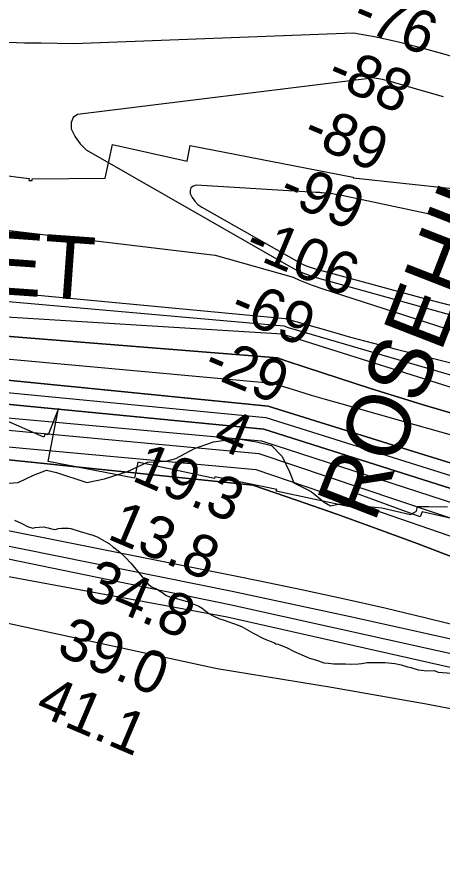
# Model space of a CAD drawing. Extents: x 3279314 to 3317160, y 734079 to 759431.
# Drawn here: x 3288528 to 3289202, y 752535 to 753859 of the extents above; entities that cross this region are included whole.
import ezdxf

# ---------------------------------------------------------------- set-up
doc = ezdxf.new("R2010")
doc.units = 0
for name, color, linetype in [('V-RIVR-EDGE', 7, 'Continuous'), ('V-RIVR-RANG', 7, 'Continuous'), ('V-RRAP-RVMT', 7, 'Continuous'), ('V-RRAP-RVMT-IDEN', 7, 'Continuous'), ('V-SITE-VEGE', 7, 'Continuous'), ('V-TOPO-DPTH', 7, 'Continuous'), ('V-TOPO-GNAM-IDEN', 7, 'Continuous'), ('V-TOPO-MAJR', 7, 'Continuous'), ('V-TOPO-MINR', 7, 'Continuous'), ('V-TOPO-WATR', 7, 'Continuous')]:
    doc.layers.add(name, color=color, linetype=linetype)

msp = doc.modelspace()

# ---------------------------------------------------------------- linework, layer by layer
at = {"layer": 'V-RIVR-EDGE'}
msp.add_lwpolyline([(3288515.4, 753120.8), (3288530.2, 753121.6), (3288554.5, 753133.3), (3288575, 753141.5), (3288591, 753137.6), (3288638.8, 753121.8), (3288666.7, 753127.4), (3288703.6, 753139), (3288735, 753154.2), (3288764.1, 753155.8), (3288779.8, 753159.7), (3288809.4, 753175.7), (3288839.4, 753186.1), (3288875.9, 753191.6), (3288907.6, 753186.4), (3288931.5, 753180.2), (3288948.4, 753162.8), (3288960.1, 753138.8), (3288966.6, 753121), (3288976.1, 753116.6), (3288994.4, 753107.5), (3289014.7, 753090.5), (3289024.7, 753084.8), (3289039.5, 753088.2), (3289106, 753081.5), (3289151.6, 753071), (3289161.2, 753076.6), (3289162.5, 753083.6), (3289180.3, 753084), (3289210.3, 753083)], dxfattribs=at)
at = {"layer": 'V-RRAP-RVMT'}
for p, q in [((3288667.8, 753603.9), (3288679.6, 753656.8)), ((3288679.6, 753656.8), (3288797.7, 753630.7)), ((3288797.7, 753630.7), (3288802.4, 753655.3)), ((3288802.4, 753655.3), (3289061, 753605.2)), ((3288435, 753617.4), (3288547.5, 753603.3)), ((3288547.5, 753603.3), (3288547.1, 753600.1)), ((3288552.4, 753600.2), (3288552.6, 753602.8)), ((3288552.6, 753602.8), (3288667.8, 753603.9)), ((3289061, 753605.2), (3289060.8, 753604.2)), ((3289060.8, 753604.2), (3289217.9, 753587.1)), ((3288547.1, 753600.1), (3288552.4, 753600.2)), ((3288594, 753238.9), (3288577.5, 753197.1)), ((3288577.7, 753155.1), (3288594, 753238.9)), ((3288570.6, 753193.5), (3288493.1, 753227.4)), ((3288573, 753198.9), (3288570.6, 753193.5)), ((3288577.5, 753197.1), (3288573, 753198.9)), ((3288714.7, 753128.4), (3288577.7, 753155.1)), ((3288719.9, 753154.1), (3288714.7, 753128.4)), ((3288841.2, 753128), (3288719.9, 753154.1)), ((3288841.7, 753130.5), (3288841.2, 753128)), ((3288939.7, 753110.6), (3288841.7, 753130.5)), ((3288939.1, 753108), (3288939.7, 753110.6)), ((3289055.2, 753083.4), (3288939.1, 753108)), ((3289060.1, 753106.4), (3289055.2, 753083.4)), ((3289167.1, 753067.5), (3289060.1, 753106.4)), ((3289170.2, 753075.4), (3289167.1, 753067.5)), ((3289271.5, 753052.3), (3289170.2, 753075.4))]:
    msp.add_line(p, q, dxfattribs=at)
at = {"layer": 'V-SITE-VEGE'}
for points in [[(3288524.4, 753062.3), (3288530.2, 753059.6), (3288534.1, 753058.1), (3288537.2, 753056.5), (3288545, 753052.3), (3288553.2, 753049.6), (3288557.1, 753050.4), (3288563.3, 753051.2), (3288571.1, 753051.3), (3288574.6, 753050.5), (3288577.7, 753050.1), (3288582.8, 753048.6), (3288586.3, 753047.8), (3288589.8, 753047.5), (3288593.7, 753048.7), (3288598.7, 753049.5), (3288603.8, 753049.5), (3288610.1, 753049.7), (3288613.4, 753048.7), (3288626.7, 753044.8), (3288648.4, 753038.3), (3288655.1, 753035.6), (3288675.1, 753024.6), (3288680.7, 753019.6), (3288683.5, 753018), (3288694.1, 753009.1), (3288700.2, 753003.1), (3288708.6, 752994.2), (3288714.2, 752987.1), (3288735.9, 752960.6), (3288742.6, 752956.1), (3288748.2, 752954), (3288757.7, 752947.9), (3288764.3, 752943.5), (3288772.1, 752939.7), (3288778.8, 752938.6), (3288797.7, 752933.1), (3288816.6, 752926), (3288821.6, 752922.7), (3288832.2, 752914.5), (3288838.9, 752910.6), (3288848.9, 752905.7), (3288855, 752904.1), (3288878.9, 752895.9), (3288885, 752893.1), (3288903.4, 752882.7), (3288920.1, 752874.4), (3288936.2, 752867.9), (3288938.4, 752866.2), (3288941.8, 752865.7), (3288956.2, 752859.7), (3288966.2, 752854.7)], [(3288966.2, 752854.7), (3288991.8, 752843.8), (3289001.3, 752841), (3289005.7, 752839.4), (3289014.1, 752836.1), (3289021.8, 752835.6), (3289030.2, 752834.6), (3289048.5, 752834.7), (3289058.5, 752834.2), (3289069, 752834.8), (3289074.6, 752835.3), (3289082.9, 752836.5), (3289111.7, 752836.7), (3289126.7, 752835.1), (3289136.7, 752832.9), (3289146.7, 752829.6), (3289152.3, 752828.6), (3289163.9, 752825.3), (3289177.8, 752823.7), (3289188.9, 752823.8), (3289195.6, 752821.6), (3289216.7, 752820)]]:
    msp.add_lwpolyline(points, dxfattribs=at)
at = {"layer": 'V-TOPO-DPTH'}
for p, q in [((3288941, 753319), (3287692.6, 753419.3)), ((3288941, 753319), (3287692.6, 753419.3)), ((3288954.4, 753314.3), (3288941, 753319)), ((3288954.4, 753314.3), (3288941, 753319)), ((3288986.2, 753303.7), (3288954.4, 753314.3)), ((3288986.2, 753303.7), (3288954.4, 753314.3)), ((3289088.3, 753270.8), (3288986.2, 753303.7)), ((3289088.3, 753270.8), (3288986.2, 753303.7)), ((3289171.5, 753244.9), (3289088.3, 753270.8)), ((3289171.5, 753244.9), (3289088.3, 753270.8)), ((3289255, 753220.1), (3289171.5, 753244.9)), ((3289255, 753220.1), (3289171.5, 753244.9))]:
    msp.add_line(p, q, dxfattribs=at)
for points in [[(3287702, 753391.4), (3288933.2, 753278.8)], [(3287702, 753391.4), (3288933.2, 753278.8)], [(3288926.2, 753242.7), (3287671.1, 753367.5)], [(3288926.2, 753242.7), (3287671.1, 753367.5)], [(3287642.3, 753330), (3288919.1, 753206.3)], [(3288919.1, 753206.3), (3287642.3, 753330)], [(3287613, 753288.7), (3288911.6, 753167.8)], [(3287613, 753288.7), (3288911.6, 753167.8)], [(3288933.2, 753278.8), (3288950.3, 753273.6), (3288972.4, 753266.8), (3288994.5, 753260.2), (3289016.7, 753253.7), (3289038.9, 753247.3), (3289158.2, 753213.4), (3289240.1, 753190.3), (3289322.1, 753167.4), (3289404.1, 753144.7), (3289486.2, 753122.2), (3290053.7, 752967.9), (3290075.8, 752962), (3290097.9, 752956.2), (3290120, 752950.6), (3290331.6, 752827.9), (3290344.6, 752819.8), (3290357.6, 752811.6), (3290370.6, 752803.5), (3290383.7, 752795.5), (3290396.9, 752787.9), (3290410.5, 752780.8)], [(3288933.2, 753278.8), (3288950.3, 753273.6), (3288972.4, 753266.8), (3288994.5, 753260.2), (3289016.7, 753253.7), (3289038.9, 753247.3), (3289158.2, 753213.4), (3289240.1, 753190.3), (3289322.1, 753167.4), (3289404.1, 753144.7), (3289486.2, 753122.2), (3290053.7, 752967.9), (3290075.8, 752962), (3290097.9, 752956.2), (3290120, 752950.6), (3290331.6, 752827.9), (3290344.6, 752819.8), (3290357.6, 752811.6), (3290370.6, 752803.5), (3290383.7, 752795.5), (3290396.9, 752787.9), (3290410.5, 752780.8)], [(3288901.9, 753117.5), (3287583.5, 753254.2)], [(3290430.9, 752719), (3290392, 752736.4), (3290353.5, 752754.8), (3290263.7, 752799.8), (3290256.1, 752803.7), (3290248.6, 752807.8), (3290241.2, 752812.1), (3290233.9, 752816.4), (3290226.5, 752820.8), (3290219.1, 752824.9), (3290211.5, 752828.7), (3290203.8, 752832.4), (3290134.3, 752863.5), (3290108.6, 752874.4), (3290082.7, 752884.7), (3290056.4, 752894), (3290029.8, 752902.6), (3289712.1, 752999.7), (3289575.3, 753041.6), (3289438.5, 753083.6), (3289301.7, 753125.9), (3289165, 753168.3), (3288926.2, 753242.7)], [(3290430.9, 752719), (3290392, 752736.4), (3290353.5, 752754.8), (3290263.7, 752799.8), (3290256.1, 752803.7), (3290248.6, 752807.8), (3290241.2, 752812.1), (3290233.9, 752816.4), (3290226.5, 752820.8), (3290219.1, 752824.9), (3290211.5, 752828.7), (3290203.8, 752832.4), (3290134.3, 752863.5), (3290108.6, 752874.4), (3290082.7, 752884.7), (3290056.4, 752894), (3290029.8, 752902.6), (3289712.1, 752999.7), (3289575.3, 753041.6), (3289438.5, 753083.6), (3289301.7, 753125.9), (3289165, 753168.3), (3288926.2, 753242.7)], [(3288919.1, 753206.3), (3289896.3, 752896.3)], [(3289896.3, 752896.3), (3288919.1, 753206.3)], [(3288911.6, 753167.8), (3289352, 753019.6), (3289470.5, 752979.4), (3289588.8, 752938.7), (3289706.9, 752897.2), (3289824.8, 752855.3), (3290024.6, 752783.7), (3290042.5, 752777.1), (3290060.2, 752770.2), (3290077.8, 752762.9), (3290095.2, 752755.3), (3290137.3, 752736.5), (3290146.1, 752732.7), (3290154.9, 752728.9), (3290163.8, 752725.3), (3290172.7, 752721.7), (3290181.6, 752718.2), (3290190.5, 752714.8), (3290199.5, 752711.4), (3290208.4, 752708), (3290373.4, 752645.8), (3290413, 752631.1)], [(3288911.6, 753167.8), (3289352, 753019.6), (3289470.5, 752979.4), (3289588.8, 752938.7), (3289706.9, 752897.2), (3289824.8, 752855.3), (3290024.6, 752783.7), (3290042.5, 752777.1), (3290060.2, 752770.2), (3290077.8, 752762.9), (3290095.2, 752755.3), (3290137.3, 752736.5), (3290146.1, 752732.7), (3290154.9, 752728.9), (3290163.8, 752725.3), (3290172.7, 752721.7), (3290181.6, 752718.2), (3290190.5, 752714.8), (3290199.5, 752711.4), (3290208.4, 752708), (3290373.4, 752645.8), (3290413, 752631.1)], [(3290439.6, 752571.9), (3290399.1, 752586.8), (3290392.6, 752589.2), (3290348.9, 752605.7), (3290305.1, 752621.9), (3290261.2, 752637.6), (3290217.1, 752653.1), (3290123.8, 752685.3), (3290087.3, 752697.5), (3290050.6, 752709.2), (3290013.8, 752720.1), (3289976.7, 752730.6), (3289351.3, 752951.4), (3289314.3, 752966.9), (3289225.7, 753001), (3289162.3, 753025), (3289098.7, 753048.6), (3289034.8, 753071.4), (3288970.8, 753093.8), (3288901.9, 753117.5)]]:
    msp.add_lwpolyline(points, dxfattribs=at)
at = {"layer": 'V-TOPO-MAJR'}
for points in [[(3289918.8, 753390), (3289042.9, 753576.1), (3289037.9, 753577.1), (3289033, 753577.9), (3289028, 753578.7), (3289022.9, 753579.3), (3289011.9, 753580.5), (3289010.6, 753580.6), (3289009.4, 753580.7), (3289008.1, 753580.8), (3289006.8, 753580.8), (3289005.5, 753580.9), (3289004.2, 753580.9), (3289002.9, 753581), (3289001.6, 753581.1), (3288812.1, 753592.5), (3288807.2, 753591), (3288803.8, 753588.5), (3288802.4, 753584.4), (3288802.5, 753579.3), (3288805.8, 753572.9), (3288809.9, 753567), (3288815, 753562.2), (3288821, 753557.9), (3288974.7, 753470.7), (3288980.5, 753467.7), (3288986.5, 753465), (3288992.6, 753462.7), (3288998.9, 753460.8), (3289173.7, 753413.2), (3289267.8, 753388.8)], [(3287687.9, 753434.7), (3288948.4, 753357.4)], [(3288948.4, 753357.4), (3288951.6, 753356.2), (3288964.7, 753351.9), (3289520.1, 753176.8), (3289617, 753147.1), (3289714.2, 753118.6), (3289811.8, 753091.8), (3289909.8, 753066.1), (3290094.5, 753019.4), (3290100.4, 753018), (3290106.3, 753016.8), (3290112.3, 753015.7), (3290118.2, 753014.8), (3290667.7, 752762.8)], [(3287547.5, 753199.7), (3288865.2, 752928.8)], [(3288865.2, 752928.8), (3289444.6, 752800.1)]]:
    msp.add_lwpolyline(points, dxfattribs=at)
at = {"layer": 'V-TOPO-MINR'}
for p, q in [((3287692.6, 753419.3), (3288941, 753319)), ((3288941, 753319), (3288954.4, 753314.3)), ((3288954.4, 753314.3), (3288986.2, 753303.7)), ((3288986.2, 753303.7), (3289088.3, 753270.8)), ((3289088.3, 753270.8), (3289171.5, 753244.9)), ((3289171.5, 753244.9), (3289255, 753220.1))]:
    msp.add_line(p, q, dxfattribs=at)
for points in [[(3291155.4, 752839), (3291098.9, 752862.9), (3291008.7, 752942.3), (3290845.1, 753101), (3290636.4, 753259.8), (3290266.7, 753469.8), (3290044.4, 753552.8), (3290008.7, 753563.3), (3289972.9, 753573.8), (3289203, 753800.6), (3289167.9, 753810.2), (3289132.6, 753819.1), (3289097.1, 753826.7), (3289061.3, 753833.4), (3288618.3, 753816.6), (3288592.5, 753817), (3288566.7, 753817.3), (3288565.5, 753817.3), (3288540.3, 753817.7), (3288515, 753818.3), (3288489.9, 753819.4), (3288474.9, 753820.2)], [(3289203.9, 753732.7), (3289179.8, 753739.6), (3289155.7, 753746.4), (3289113.9, 753758.3), (3289110.7, 753759.1), (3289107.5, 753759.9), (3289104.2, 753760.6), (3289101, 753761.2), (3289091.4, 753762.8), (3289090.6, 753762.9), (3289089.9, 753762.9), (3289089.2, 753762.9), (3289088.5, 753762.8), (3289087.8, 753762.7), (3289087.1, 753762.4), (3289086.5, 753762.1), (3289085.9, 753761.7), (3288624.1, 753704.7), (3288617.2, 753699.9), (3288614.4, 753691.9), (3288614.4, 753681.9), (3288620.5, 753669.2), (3288628.2, 753657.9), (3288638, 753648.4), (3288957.7, 753465.3), (3288969.3, 753459.2), (3288981.2, 753453.8), (3288993.5, 753449.2), (3289006, 753445.2), (3289715.4, 753248.6)], [(3287736.7, 753526.1), (3287807.9, 753515.5), (3288149.8, 753509), (3288503.2, 753522.2), (3288842.2, 753481.8), (3288965.8, 753447)], [(3287736.7, 753500.4), (3287749.3, 753494.8), (3288953.2, 753381.7)], [(3287755.9, 753475.3), (3288950.8, 753369.7)], [(3288965.8, 753447), (3288975.9, 753442.2), (3288994.1, 753434.8), (3289012.7, 753428.2), (3289305.7, 753334.1), (3289439.9, 753292.6), (3290099, 753114.1), (3290282.6, 753045.8), (3290819, 752815.6), (3291131.4, 752684.8)], [(3287702, 753391.4), (3288933.2, 753278.8)], [(3288953.2, 753381.7), (3289020.6, 753362.2), (3289056.7, 753352), (3289092.8, 753342.2), (3289129.1, 753333), (3289165.5, 753324.1), (3290115.9, 753083), (3290477.3, 752926.7), (3290793.5, 752778.9), (3291129.6, 752671.2)], [(3287671.1, 753367.5), (3288926.2, 753242.7)], [(3288950.8, 753369.7), (3288957.9, 753367.4), (3289817.4, 753116.4), (3289865.7, 753103.4), (3289914.3, 753091.6), (3289963.4, 753081.8), (3290141.2, 753034.9), (3290463.1, 752895.6), (3290810.3, 752736.5), (3291125.3, 752656.2)], [(3287665.3, 753346.3), (3288922.6, 753224.5)], [(3287642.3, 753330), (3288919.1, 753206.3)], [(3287652.2, 753302.2), (3288915.5, 753187.9)], [(3288933.2, 753278.8), (3288950.3, 753273.6), (3288972.4, 753266.8), (3288994.5, 753260.2), (3289016.7, 753253.7), (3289038.9, 753247.3), (3289158.2, 753213.4), (3289240.1, 753190.3), (3289322.1, 753167.4), (3289404.1, 753144.7), (3289486.2, 753122.2), (3290053.7, 752967.9), (3290075.8, 752962), (3290097.9, 752956.2), (3290120, 752950.6), (3290331.6, 752827.9), (3290344.6, 752819.8), (3290357.6, 752811.6), (3290370.6, 752803.5), (3290383.7, 752795.5), (3290396.9, 752787.9), (3290410.5, 752780.8)], [(3287621, 753259.9), (3288906.7, 753142.6)], [(3287583.5, 753254.2), (3288901.9, 753117.5)], [(3288926.2, 753242.7), (3289165, 753168.3), (3289301.7, 753125.9), (3289438.5, 753083.6), (3289575.3, 753041.6), (3289712.1, 752999.7), (3290029.8, 752902.6), (3290056.4, 752894), (3290082.7, 752884.7), (3290108.6, 752874.4), (3290134.3, 752863.5), (3290203.8, 752832.4), (3290211.5, 752828.7), (3290219.1, 752824.9), (3290226.5, 752820.8), (3290233.9, 752816.4), (3290241.2, 752812.1), (3290248.6, 752807.8), (3290256.1, 752803.7), (3290263.7, 752799.8), (3290353.5, 752754.8), (3290392, 752736.4), (3290430.9, 752719)], [(3287592, 753229.8), (3288874, 752973.9)], [(3288922.6, 753224.5), (3289490.3, 753046.2)], [(3287590.1, 753207.9), (3288869.3, 752949.7)], [(3288919.1, 753206.3), (3289896.3, 752896.3)], [(3288915.5, 753187.9), (3289782, 752906.2), (3289829.7, 752890.3), (3289877.2, 752873.9), (3289924.4, 752856.8), (3289971.5, 752839.2), (3289999.2, 752828.6), (3290032.1, 752815.5), (3290064.7, 752801.9), (3290097, 752787.4), (3290129.1, 752772.4), (3290196.1, 752740.1), (3290211.2, 752733), (3290226.5, 752726.2), (3290242, 752719.7), (3290257.5, 752713.5), (3290273.2, 752707.4), (3290288.8, 752701.5), (3290304.5, 752695.6), (3290320.2, 752689.7), (3290454.6, 752639.8)], [(3287568.6, 753147.8), (3288861.4, 752909.2)], [(3288906.7, 753142.6), (3289091.4, 753079.5), (3289210.9, 753038.5), (3289330.3, 752997.4), (3289449.6, 752956), (3289568.9, 752914.3), (3290046.5, 752747), (3290051.4, 752745.2), (3290056.3, 752743.4), (3290061.2, 752741.4), (3290066, 752739.4), (3290078.5, 752734), (3290080.9, 752733), (3290083.4, 752731.9), (3290085.9, 752730.9), (3290088.4, 752729.9), (3290090.9, 752728.9), (3290093.4, 752727.9), (3290095.9, 752727), (3290098.4, 752726), (3290292.9, 752651.6), (3290335.1, 752635.6), (3290377.4, 752619.9), (3290419.8, 752604.4)], [(3287495.5, 753119.9), (3288845.5, 752827.1)], [(3288901.9, 753117.5), (3288970.8, 753093.8), (3289034.8, 753071.4), (3289098.7, 753048.6), (3289162.3, 753025), (3289225.7, 753001), (3289314.3, 752966.9), (3289351.3, 752951.4), (3289976.7, 752730.6), (3290013.8, 752720.1), (3290050.6, 752709.2), (3290087.3, 752697.5), (3290123.8, 752685.3), (3290217.1, 752653.1), (3290261.2, 752637.6), (3290305.1, 752621.9), (3290348.9, 752605.7), (3290392.6, 752589.2), (3290399.1, 752586.8), (3290439.6, 752571.9)], [(3288874, 752973.9), (3288913.2, 752966.1), (3288979.2, 752952.5), (3289045.2, 752938.3), (3289110.9, 752923.2), (3289176.5, 752907.5), (3289990.9, 752706.7), (3290019.4, 752699.2), (3290047.7, 752691.2), (3290075.7, 752682.4), (3290103.6, 752673), (3290149.4, 752656.8), (3290193.4, 752640.8), (3290237.2, 752624.3), (3290280.7, 752607), (3290324, 752589.2), (3290346.9, 752579.6), (3290378.7, 752566.7), (3290410.9, 752554.5)], [(3288869.3, 752949.7), (3289061.3, 752908.3), (3289205.9, 752876.5), (3289350.4, 752843.9), (3289494.6, 752810), (3289638.6, 752775.3), (3290004.9, 752685.4), (3290024.9, 752680.1), (3290044.9, 752674.4), (3290064.6, 752668), (3290084.2, 752661.2), (3290109.1, 752652), (3290140.9, 752639.8), (3290172.4, 752627.1), (3290203.6, 752613.4), (3290234.5, 752599.2), (3290291.1, 752572.3), (3290314.9, 752561.5), (3290339, 752551.3), (3290363.5, 752542.1), (3290388.2, 752533.6), (3290413, 752525.3)], [(3288861.4, 752909.2), (3289871.7, 752681.2)], [(3288845.5, 752827.1), (3289026.7, 752797.5), (3289179.8, 752770.6), (3289332.4, 752741.3), (3289484.3, 752708.5), (3289635.7, 752673.2), (3289988.5, 752586.7), (3290008.4, 752581.1), (3290028, 752574.7), (3290047.2, 752567.1), (3290066.1, 752558.6), (3290094.8, 752544.5), (3290099.9, 752542.1), (3290105, 752539.7), (3290110.2, 752537.5), (3290115.5, 752535.4), (3290120.7, 752533.3), (3290125.9, 752531.1), (3290131.1, 752528.8), (3290136.2, 752526.4), (3290139.3, 752524.9), (3290142.2, 752521.6), (3291142.8, 752203.9)]]:
    msp.add_lwpolyline(points, dxfattribs=at)
at = {"layer": 'V-TOPO-WATR'}
for points in [[(3287613, 753288.7), (3288911.6, 753167.8)], [(3288911.6, 753167.8), (3289352, 753019.6), (3289470.5, 752979.4), (3289588.8, 752938.7), (3289706.9, 752897.2), (3289824.8, 752855.3), (3290024.6, 752783.7), (3290042.5, 752777.1), (3290060.2, 752770.2), (3290077.8, 752762.9), (3290095.2, 752755.3), (3290137.3, 752736.5), (3290146.1, 752732.7), (3290154.9, 752728.9), (3290163.8, 752725.3), (3290172.7, 752721.7), (3290181.6, 752718.2), (3290190.5, 752714.8), (3290199.5, 752711.4), (3290208.4, 752708), (3290373.4, 752645.8), (3290413, 752631.1)]]:
    msp.add_lwpolyline(points, dxfattribs=at)

# ---------------------------------------------------------------- texts
at = {"layer": 'V-RIVR-RANG'}
for s, rotation, p in [('-76', 337.241, (3289056, 753846.6)), ('-88', 337.241, (3289016.1, 753754.9)), ('-89', 337.241, (3288977.9, 753662.5)), ('-99', 337.241, (3288940, 753569.9)), ('-106', 337.241, (3288885.8, 753484.2)), ('-69', 337.241, (3288862.2, 753385.7)), ('-29', 337.241, (3288820.4, 753294.8)), ('4', 337.241, (3288835.5, 753180)), ('19.3', 336.9683, (3288708.1, 753125.6)), ('13.8', 336.9683, (3288669.3, 753033.5)), ('34.8', 336.9683, (3288630.4, 752941.4)), ('39.0', 336.9683, (3288588.8, 752850.4)), ('41.1', 336.9683, (3288554.8, 752756.2))]:
    msp.add_text(s, height=67, rotation=rotation, dxfattribs=at).set_placement(p)
at = {"layer": 'V-RRAP-RVMT-IDEN'}
msp.add_text('REVET', height=100, rotation=355.9244, dxfattribs=at).set_placement((3288203.1, 753441.3))
at = {"layer": 'V-TOPO-GNAM-IDEN'}
msp.add_text('ROSEHILL LDG.', height=100, rotation=68.7363, dxfattribs=at).set_placement((3289094.2, 753056))

doc.saveas('drawing.dxf')
